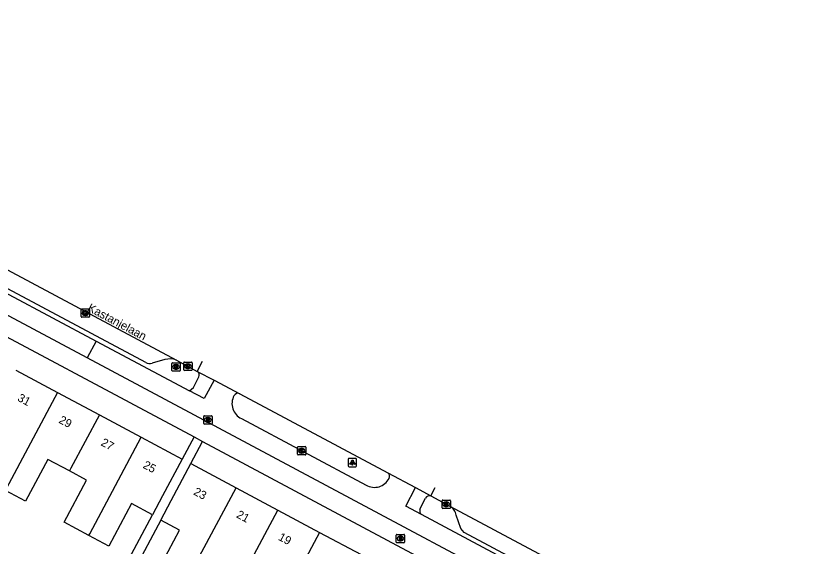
# Model space of a CAD drawing. Extents: x 159265 to 160143, y 383413 to 384319.
# Drawn here: x 159869.9 to 159965.3, y 383916 to 383979.7 of the extents above; entities that cross this region are included whole.
import ezdxf

# ---------------------------------------------------------------- set-up
doc = ezdxf.new("R2010")
doc.units = 0
for name, color, linetype in [('IMGEO_Brandkraan', 7, 'Continuous'), ('IMGEO_Fietspad_gesloten', 7, 'Continuous'), ('IMGEO_Kolk', 7, 'Continuous'), ('IMGEO_Lichtpunt', 7, 'Continuous'), ('IMGEO_Openbare_ruimte_label', 7, 'Continuous'), ('IMGEO_Pand', 7, 'Continuous'), ('IMGEO_Pand_nummerreeks', 7, 'Continuous'), ('IMGEO_Parkeervlak_open', 7, 'Continuous'), ('IMGEO_Rijbaan_lokaal_gesloten', 7, 'Continuous'), ('IMGEO_Rioolput', 7, 'Continuous'), ('IMGEO_Voetpad_open', 7, 'Continuous')]:
    doc.layers.add(name, color=color, linetype=linetype)

msp = doc.modelspace()

# ---------------------------------------------------------------- linework, layer by layer
at = {"layer": 'IMGEO_Brandkraan'}
for p, q in [((159915.567, 383916.513), (159915.567, 383917.365)), ((159915.642, 383917.439), (159916.494, 383917.439)), ((159916.055, 383917.219), (159916.08, 383917.219)), ((159916.568, 383917.365), (159916.568, 383916.513)), ((159916.494, 383916.439), (159915.642, 383916.439)), ((159916.078, 383916.659), (159916.053, 383916.659))]:
    msp.add_line(p, q, dxfattribs=at)
for points in [[(159915.567, 383916.513), (159915.567, 383917.365)], [(159915.642, 383917.439), (159916.494, 383917.439)], [(159915.915, 383917.139), (159915.915, 383916.739), (159916.128, 383916.739)], [(159916.146, 383917.139), (159915.915, 383917.139)], [(159916.094, 383917.058), (159916.04, 383917.058), (159916.04, 383916.982)], [(159916.568, 383917.365), (159916.568, 383916.513)], [(159916.494, 383916.439), (159915.642, 383916.439)], [(159916.04, 383916.982), (159916.093, 383916.982)], [(159916.102, 383916.906), (159916.04, 383916.906), (159916.04, 383916.825)], [(159916.04, 383916.825), (159916.102, 383916.825)]]:
    msp.add_lwpolyline(points, dxfattribs=at)
for centre, radius, start, end in [((159915.644, 383917.363), 0.0765, 91.55205, 178.44795), ((159915.644, 383917.363), 0.0765, 91.55205, 178.44795), ((159916.095, 383917.02), 0.0379, 267.82845, 90.93552), ((159916.15, 383916.994), 0.145, 59.4692, 91.53667), ((159916.175, 383917.041), 0.0922, 285.51372, 58.15012), ((159916.492, 383917.363), 0.0765, 1.55205, 88.44795), ((159916.492, 383917.363), 0.0765, 1.55205, 88.44795), ((159915.644, 383916.515), 0.0765, 181.55205, 268.44795), ((159915.644, 383916.515), 0.0765, 181.55205, 268.44795), ((159916.103, 383916.865), 0.0404, 269.87594, 90.50774), ((159916.134, 383916.99), 0.251, 268.66757, 293.53466), ((159916.18, 383916.849), 0.105, 301.31148, 78.98903), ((159916.492, 383916.515), 0.0765, 271.55205, 358.44795), ((159916.492, 383916.515), 0.0765, 271.55205, 358.44795)]:
    msp.add_arc(centre, radius, start, end, dxfattribs=at)
for centre, major_axis, ratio, start_param, end_param in [((159916.054, 383916.939), (-0.387, 0.002), 0.722429, 4.712389, 7.853982), ((159916.079, 383916.939), (-0.39, 0.002), 0.717154, 1.570796, 4.712389)]:
    msp.add_ellipse(centre, major_axis=major_axis, ratio=ratio, start_param=start_param, end_param=end_param, dxfattribs=at)
at = {"layer": 'IMGEO_Fietspad_gesloten'}
for points in [[(159878.488, 383938.609), (159818.103, 383970.845), (159815.384, 383972.277), (159811.759, 383973.873), (159806.209, 383976.854), (159802.382, 383978.898)], [(159807.769, 383978.315), (159811.755, 383976.132), (159812.762, 383975.674), (159812.887, 383975.929), (159817.239, 383973.81), (159821.924, 383971.407), (159879.571, 383940.642)], [(159879.571, 383940.642), (159878.488, 383938.609)], [(159879.571, 383940.642), (159890.781, 383934.659)], [(159961.003, 383894.56), (159878.488, 383938.609)], [(159893.727, 383935.935), (159892.539, 383933.733), (159890.781, 383934.659)], [(159896.999, 383931.341), (159911.954, 383923.349)], [(159918.588, 383919.812), (159916.706, 383920.813), (159917.898, 383923.047)], [(160080.53, 383833.461), (160018.359, 383866.492), (159968.689, 383893.037), (159961.28, 383896.996), (159918.588, 383919.812)]]:
    msp.add_lwpolyline(points, dxfattribs=at)
for centre, radius, start, end in [((159896.592, 383933.815), 0.552, 65.22761, 152.35699), ((159897.838, 383933.129), 1.975, 151.49609, 244.84412), ((159914.279, 383924.412), 0.503, 329.76886, 53.58684), ((159912.951, 383925.06), 1.98, 239.78454, 332.9271)]:
    msp.add_arc(centre, radius, start, end, dxfattribs=at)
at = {"layer": 'IMGEO_Kolk'}
for p, q in [((159877.772, 383943.574), (159877.772, 383944.426)), ((159877.847, 383944.5), (159878.699, 383944.5)), ((159878.26, 383944.28), (159878.285, 383944.28)), ((159878.773, 383944.426), (159878.773, 383943.574)), ((159878.699, 383943.5), (159877.847, 383943.5)), ((159878.283, 383943.72), (159878.258, 383943.72)), ((159890.151, 383938.109), (159891.003, 383938.109)), ((159890.076, 383937.183), (159890.076, 383938.035)), ((159891.003, 383937.109), (159890.151, 383937.109)), ((159890.587, 383937.329), (159890.562, 383937.329)), ((159890.564, 383937.889), (159890.589, 383937.889)), ((159891.077, 383938.035), (159891.077, 383937.183)), ((159903.728, 383927.051), (159903.728, 383927.903)), ((159903.803, 383927.977), (159904.655, 383927.977)), ((159904.216, 383927.757), (159904.241, 383927.757)), ((159904.729, 383927.903), (159904.729, 383927.051)), ((159904.655, 383926.977), (159903.803, 383926.977)), ((159904.239, 383927.197), (159904.214, 383927.197)), ((159921.066, 383920.626), (159921.066, 383921.478)), ((159921.141, 383921.552), (159921.993, 383921.552)), ((159921.554, 383921.332), (159921.579, 383921.332)), ((159922.067, 383921.478), (159922.067, 383920.626)), ((159921.993, 383920.552), (159921.141, 383920.552)), ((159921.577, 383920.772), (159921.552, 383920.772))]:
    msp.add_line(p, q, dxfattribs=at)
for points in [[(159877.772, 383943.574), (159877.772, 383944.426)], [(159877.847, 383944.5), (159878.699, 383944.5)], [(159878.093, 383944.2), (159878.216, 383944.2), (159878.216, 383944.049), (159878.346, 383944.2), (159878.51, 383944.2), (159878.364, 383944.049), (159878.517, 383943.8), (159878.365, 383943.8), (159878.28, 383943.964), (159878.216, 383943.897), (159878.216, 383943.8), (159878.093, 383943.8), (159878.093, 383944.2)], [(159878.773, 383944.426), (159878.773, 383943.574)], [(159878.699, 383943.5), (159877.847, 383943.5)], [(159890.151, 383938.109), (159891.003, 383938.109)], [(159890.076, 383937.183), (159890.076, 383938.035)], [(159891.003, 383937.109), (159890.151, 383937.109)], [(159890.397, 383937.809), (159890.52, 383937.809), (159890.52, 383937.658), (159890.65, 383937.809), (159890.814, 383937.809), (159890.668, 383937.658), (159890.821, 383937.409), (159890.669, 383937.409), (159890.584, 383937.573), (159890.52, 383937.506), (159890.52, 383937.409), (159890.397, 383937.409), (159890.397, 383937.809)], [(159891.077, 383938.035), (159891.077, 383937.183)], [(159903.728, 383927.051), (159903.728, 383927.903)], [(159903.803, 383927.977), (159904.655, 383927.977)], [(159904.049, 383927.677), (159904.172, 383927.677), (159904.172, 383927.526), (159904.302, 383927.677), (159904.466, 383927.677), (159904.32, 383927.526), (159904.473, 383927.277), (159904.321, 383927.277), (159904.236, 383927.441), (159904.172, 383927.374), (159904.172, 383927.277), (159904.049, 383927.277), (159904.049, 383927.677)], [(159904.729, 383927.903), (159904.729, 383927.051)], [(159904.655, 383926.977), (159903.803, 383926.977)], [(159921.066, 383920.626), (159921.066, 383921.478)], [(159921.141, 383921.552), (159921.993, 383921.552)], [(159921.387, 383921.252), (159921.51, 383921.252), (159921.51, 383921.101), (159921.64, 383921.252), (159921.804, 383921.252), (159921.658, 383921.101), (159921.811, 383920.852), (159921.659, 383920.852), (159921.574, 383921.016), (159921.51, 383920.949), (159921.51, 383920.852), (159921.387, 383920.852), (159921.387, 383921.252)], [(159922.067, 383921.478), (159922.067, 383920.626)], [(159921.993, 383920.552), (159921.141, 383920.552)]]:
    msp.add_lwpolyline(points, dxfattribs=at)
for centre, start, end in [((159877.849, 383944.424), 91.55205, 178.44795), ((159877.849, 383944.424), 91.55205, 178.44795), ((159878.697, 383944.424), 1.55205, 88.44795), ((159878.697, 383944.424), 1.55205, 88.44795), ((159877.849, 383943.576), 181.55205, 268.44795), ((159877.849, 383943.576), 181.55205, 268.44795), ((159878.697, 383943.576), 271.55205, 358.44795), ((159878.697, 383943.576), 271.55205, 358.44795), ((159890.153, 383938.033), 91.55205, 178.44795), ((159890.153, 383938.033), 91.55205, 178.44795), ((159891.001, 383938.033), 1.55205, 88.44795), ((159891.001, 383938.033), 1.55205, 88.44795), ((159890.153, 383937.185), 181.55205, 268.44795), ((159890.153, 383937.185), 181.55205, 268.44795), ((159891.001, 383937.185), 271.55205, 358.44795), ((159891.001, 383937.185), 271.55205, 358.44795), ((159903.805, 383927.901), 91.55205, 178.44795), ((159903.805, 383927.901), 91.55205, 178.44795), ((159904.653, 383927.901), 1.55205, 88.44795), ((159904.653, 383927.901), 1.55205, 88.44795), ((159903.805, 383927.053), 181.55205, 268.44795), ((159903.805, 383927.053), 181.55205, 268.44795), ((159904.653, 383927.053), 271.55205, 358.44795), ((159904.653, 383927.053), 271.55205, 358.44795), ((159921.143, 383921.476), 91.55205, 178.44795), ((159921.143, 383921.476), 91.55205, 178.44795), ((159921.991, 383921.476), 1.55205, 88.44795), ((159921.991, 383921.476), 1.55205, 88.44795), ((159921.143, 383920.628), 181.55205, 268.44795), ((159921.143, 383920.628), 181.55205, 268.44795), ((159921.991, 383920.628), 271.55205, 358.44795), ((159921.991, 383920.628), 271.55205, 358.44795)]:
    msp.add_arc(centre, 0.0765, start, end, dxfattribs=at)
for centre, major_axis, ratio, start_param, end_param in [((159878.259, 383944), (-0.387, 0.002), 0.722429, 4.712389, 7.853982), ((159878.284, 383944), (-0.39, 0.002), 0.717154, 1.570796, 4.712389), ((159890.563, 383937.609), (-0.387, 0.002), 0.722429, 4.712389, 7.853982), ((159890.588, 383937.609), (-0.39, 0.002), 0.717154, 1.570796, 4.712389), ((159904.215, 383927.477), (-0.387, 0.002), 0.722429, 4.712389, 7.853982), ((159904.24, 383927.477), (-0.39, 0.002), 0.717154, 1.570796, 4.712389), ((159921.553, 383921.052), (-0.387, 0.002), 0.722429, 4.712389, 7.853982), ((159921.578, 383921.052), (-0.39, 0.002), 0.717154, 1.570796, 4.712389)]:
    msp.add_ellipse(centre, major_axis=major_axis, ratio=ratio, start_param=start_param, end_param=end_param, dxfattribs=at)
at = {"layer": 'IMGEO_Lichtpunt'}
for p, q in [((159909.813, 383926.464), (159909.813, 383925.657)), ((159909.813, 383926.464), (159909.813, 383925.657)), ((159910.715, 383926.559), (159909.907, 383926.559)), ((159910.715, 383926.559), (159909.907, 383926.559)), ((159910.809, 383925.657), (159910.809, 383926.464)), ((159910.809, 383925.657), (159910.809, 383926.464)), ((159909.907, 383925.563), (159910.715, 383925.563)), ((159909.907, 383925.563), (159910.715, 383925.563))]:
    msp.add_line(p, q, dxfattribs=at)
for points in [[(159910.187, 383926.128), (159910.226, 383926.1), (159910.038, 383925.838), (159910, 383925.865), (159910.187, 383926.128)], [(159910.289, 383926.08), (159910.336, 383926.08), (159910.336, 383925.758), (159910.289, 383925.758), (159910.289, 383926.08)], [(159910.399, 383926.1), (159910.437, 383926.127), (159910.624, 383925.865), (159910.585, 383925.837), (159910.399, 383926.1)]]:
    msp.add_lwpolyline(points, dxfattribs=at)
msp.add_circle((159910.312, 383926.262), 0.0994, dxfattribs=at)
for centre, start, end in [((159909.907, 383926.464), 90, 180), ((159909.907, 383926.464), 90, 180), ((159909.907, 383925.657), 180, 270), ((159909.907, 383925.657), 180, 270), ((159910.715, 383926.464), 0, 90), ((159910.715, 383926.464), 0, 90), ((159910.715, 383925.657), 270, 0), ((159910.715, 383925.657), 270, 360)]:
    msp.add_arc(centre, 0.0946, start, end, dxfattribs=at)
at = {"layer": 'IMGEO_Pand'}
for points in [[(159869.927, 383937.15), (159874.947, 383934.466)], [(159874.947, 383934.466), (159868.77, 383922.888), (159868.676, 383922.712)], [(159874.947, 383934.466), (159879.965, 383931.783)], [(159879.965, 383931.783), (159876.546, 383925.372), (159876.377, 383925.054)], [(159879.965, 383931.783), (159884.987, 383929.099)], [(159878.702, 383917.319), (159878.805, 383917.511), (159884.987, 383929.099)], [(159884.987, 383929.099), (159889.889, 383926.478)], [(159876.377, 383925.054), (159873.781, 383926.438), (159871.103, 383921.418), (159868.676, 383922.712)], [(159889.889, 383926.478), (159887.537, 383922.069), (159886.318, 383919.784)], [(159887.31, 383919.147), (159888.572, 383921.515), (159890.923, 383925.926)], [(159890.923, 383925.926), (159896.349, 383923.03)], [(159878.702, 383917.319), (159875.734, 383918.902), (159878.431, 383923.958), (159876.377, 383925.054)], [(159890.009, 383911.139), (159890.177, 383911.453), (159896.349, 383923.03)], [(159896.349, 383923.03), (159901.357, 383920.358)], [(159886.318, 383919.784), (159883.803, 383921.126), (159881.092, 383916.044), (159878.702, 383917.319)], [(159897.762, 383913.615), (159897.922, 383913.915), (159901.357, 383920.358)], [(159901.357, 383920.358), (159906.365, 383917.685)], [(159890.009, 383911.139), (159886.847, 383912.824), (159889.575, 383917.94), (159887.31, 383919.147)], [(159906.365, 383917.685), (159900.153, 383906.033), (159900.025, 383905.793)], [(159906.365, 383917.685), (159911.373, 383915.013)]]:
    msp.add_lwpolyline(points, dxfattribs=at)
at = {"layer": 'IMGEO_Parkeervlak_open'}
for points in [[(159885.523, 383938.052), (159822.09, 383971.919), (159813.13, 383976.392)], [(159887.826, 383938.407), (159886.287, 383937.986)], [(159955.407, 383900.729), (159923.72, 383917.674), (159923.321, 383918.129), (159922.778, 383919.75)]]:
    msp.add_lwpolyline(points, dxfattribs=at)
for centre, radius, start, end in [((159885.971, 383938.785), 0.859, 238.54265, 291.58259), ((159888.432, 383936.293), 2.199, 68.84515, 106.00171), ((159921.128, 383919.364), 1.694, 13.16071, 58.83639)]:
    msp.add_arc(centre, radius, start, end, dxfattribs=at)
at = {"layer": 'IMGEO_Rijbaan_lokaal_gesloten'}
for points in [[(159810.574, 383979.653), (159814.9, 383977.723), (159818.616, 383975.911), (159827.568, 383971.273), (159889.226, 383938.344)], [(159889.226, 383938.344), (159891.696, 383937.001)], [(159891.696, 383937.001), (159892.323, 383938.219)], [(159891.696, 383937.001), (159893.727, 383935.935)], [(159893.727, 383935.935), (159896.823, 383934.316)], [(159896.823, 383934.316), (159914.578, 383924.817)], [(159914.578, 383924.817), (159917.898, 383923.047)], [(159917.898, 383923.047), (159919.708, 383922.063)], [(159919.708, 383922.063), (159920.241, 383923.056)], [(159919.708, 383922.063), (159922.005, 383920.814)], [(159922.005, 383920.814), (159959.239, 383900.942)]]:
    msp.add_lwpolyline(points, dxfattribs=at)
at = {"layer": 'IMGEO_Rioolput'}
for p, q in [((159888.65, 383937.105), (159888.65, 383937.957)), ((159888.725, 383938.031), (159889.577, 383938.031)), ((159889.161, 383937.251), (159889.136, 383937.251)), ((159889.138, 383937.811), (159889.163, 383937.811)), ((159889.651, 383937.957), (159889.651, 383937.105)), ((159889.577, 383937.031), (159888.725, 383937.031)), ((159892.474, 383930.747), (159892.474, 383931.599)), ((159892.549, 383931.673), (159893.401, 383931.673)), ((159892.962, 383931.453), (159892.987, 383931.453)), ((159893.475, 383931.599), (159893.475, 383930.747)), ((159893.401, 383930.673), (159892.549, 383930.673)), ((159892.985, 383930.893), (159892.96, 383930.893))]:
    msp.add_line(p, q, dxfattribs=at)
for points in [[(159888.65, 383937.105), (159888.65, 383937.957)], [(159888.725, 383938.031), (159889.577, 383938.031)], [(159889.239, 383937.729), (159888.987, 383937.731), (159888.987, 383937.331)], [(159888.987, 383937.331), (159889.111, 383937.331), (159889.111, 383937.493), (159889.122, 383937.493)], [(159889.165, 383937.65), (159889.111, 383937.65), (159889.111, 383937.569)], [(159889.111, 383937.569), (159889.163, 383937.569)], [(159889.169, 383937.464), (159889.24, 383937.331), (159889.38, 383937.331), (159889.315, 383937.457)], [(159889.651, 383937.957), (159889.651, 383937.105)], [(159889.577, 383937.031), (159888.725, 383937.031)], [(159892.474, 383930.747), (159892.474, 383931.599)], [(159892.549, 383931.673), (159893.401, 383931.673)], [(159893.063, 383931.371), (159892.811, 383931.373), (159892.811, 383930.973)], [(159893.475, 383931.599), (159893.475, 383930.747)], [(159893.401, 383930.673), (159892.549, 383930.673)], [(159892.811, 383930.973), (159892.935, 383930.973), (159892.935, 383931.135), (159892.946, 383931.135)], [(159892.989, 383931.292), (159892.935, 383931.292), (159892.935, 383931.211)], [(159892.935, 383931.211), (159892.987, 383931.211)], [(159892.993, 383931.106), (159893.064, 383930.973), (159893.204, 383930.973), (159893.139, 383931.099)]]:
    msp.add_lwpolyline(points, dxfattribs=at)
for centre, radius, start, end in [((159888.727, 383937.955), 0.0765, 91.55205, 178.44795), ((159888.727, 383937.955), 0.0765, 91.55205, 178.44795), ((159888.727, 383937.107), 0.0765, 181.55205, 268.44795), ((159888.727, 383937.107), 0.0765, 181.55205, 268.44795), ((159889.121, 383937.44), 0.0533, 26.02933, 88.69889), ((159889.147, 383937.758), 0.19, 274.7715, 282.96867), ((159889.171, 383937.554), 0.0964, 77.00612, 93.18647), ((159889.185, 383937.611), 0.0378, 276.66336, 79.67722), ((159889.238, 383937.619), 0.109, 350.36119, 89.41601), ((159889.236, 383937.619), 0.112, 277.58423, 350.98172), ((159889.22, 383937.404), 0.108, 29.51342, 73.79051), ((159889.575, 383937.955), 0.0765, 1.55205, 88.44795), ((159889.575, 383937.955), 0.0765, 1.55205, 88.44795), ((159889.575, 383937.107), 0.0765, 271.55205, 358.44795), ((159889.575, 383937.107), 0.0765, 271.55205, 358.44795), ((159892.551, 383931.597), 0.0765, 91.55205, 178.44795), ((159892.551, 383931.597), 0.0765, 91.55205, 178.44795), ((159893.062, 383931.261), 0.109, 350.36119, 89.41601), ((159893.399, 383931.597), 0.0765, 1.55205, 88.44795), ((159893.399, 383931.597), 0.0765, 1.55205, 88.44795), ((159892.551, 383930.749), 0.0765, 181.55205, 268.44795), ((159892.551, 383930.749), 0.0765, 181.55205, 268.44795), ((159892.945, 383931.082), 0.0533, 26.02933, 88.69889), ((159892.971, 383931.4), 0.19, 274.7715, 282.96867), ((159892.995, 383931.196), 0.0964, 77.00612, 93.18647), ((159893.009, 383931.253), 0.0378, 276.66336, 79.67722), ((159893.06, 383931.261), 0.112, 277.58423, 350.98172), ((159893.044, 383931.046), 0.108, 29.51342, 73.79051), ((159893.399, 383930.749), 0.0765, 271.55205, 358.44795), ((159893.399, 383930.749), 0.0765, 271.55205, 358.44795)]:
    msp.add_arc(centre, radius, start, end, dxfattribs=at)
for centre, major_axis, ratio, start_param, end_param in [((159889.137, 383937.531), (-0.387, 0.002), 0.722429, 4.712389, 7.853982), ((159889.162, 383937.531), (-0.39, 0.002), 0.717154, 1.570796, 4.712389), ((159892.961, 383931.173), (-0.387, 0.002), 0.722429, 4.712389, 7.853982), ((159892.986, 383931.173), (-0.39, 0.002), 0.717154, 1.570796, 4.712389)]:
    msp.add_ellipse(centre, major_axis=major_axis, ratio=ratio, start_param=start_param, end_param=end_param, dxfattribs=at)
at = {"layer": 'IMGEO_Voetpad_open'}
for points in [[(159861.023, 383945.315), (159891.308, 383929.133)], [(159890.781, 383934.659), (159891.232, 383935.057), (159891.895, 383936.33)], [(159891.308, 383929.133), (159889.889, 383926.478)], [(159890.923, 383925.926), (159892.341, 383928.581)], [(159891.308, 383929.133), (159892.341, 383928.581)], [(159892.341, 383928.581), (159922.62, 383912.402)], [(159918.405, 383920.482), (159919.095, 383921.805)], [(159887.31, 383919.147), (159877.6, 383900.927), (159876.408, 383898.69), (159881.98, 383895.689), (159885.67, 383893.702), (159906.632, 383882.414), (159917.62, 383903.025)], [(159876.661, 383901.686), (159886.318, 383919.784)]]:
    msp.add_lwpolyline(points, dxfattribs=at)
for centre, radius, start, end in [((159891.434, 383936.558), 0.515, 333.6728, 59.36499), ((159919.563, 383921.549), 0.534, 74.28129, 151.36931), ((159919.064, 383920.302), 0.683, 164.72251, 225.83114)]:
    msp.add_arc(centre, radius, start, end, dxfattribs=at)

# ---------------------------------------------------------------- texts
at = {"layer": 'IMGEO_Openbare_ruimte_label'}
msp.add_text('Kastanjelaan', height=1, rotation=331.89718, dxfattribs=at).set_placement((159878.453, 383944.323))
at = {"layer": 'IMGEO_Pand_nummerreeks'}
for s, rotation, p in [('31', 331.84485, (159870.051, 383933.519)), ('29', 331.84485, (159874.999, 383930.87)), ('27', 331.84485, (159880.048, 383928.167)), ('25', 331.84485, (159885.096, 383925.465)), ('23', 331.86777, (159891.161, 383922.263)), ('21', 331.86777, (159896.308, 383919.512)), ('19', 331.86777, (159901.334, 383916.824))]:
    msp.add_text(s, height=1, rotation=rotation, dxfattribs=at).set_placement(p)

doc.saveas('drawing.dxf')
